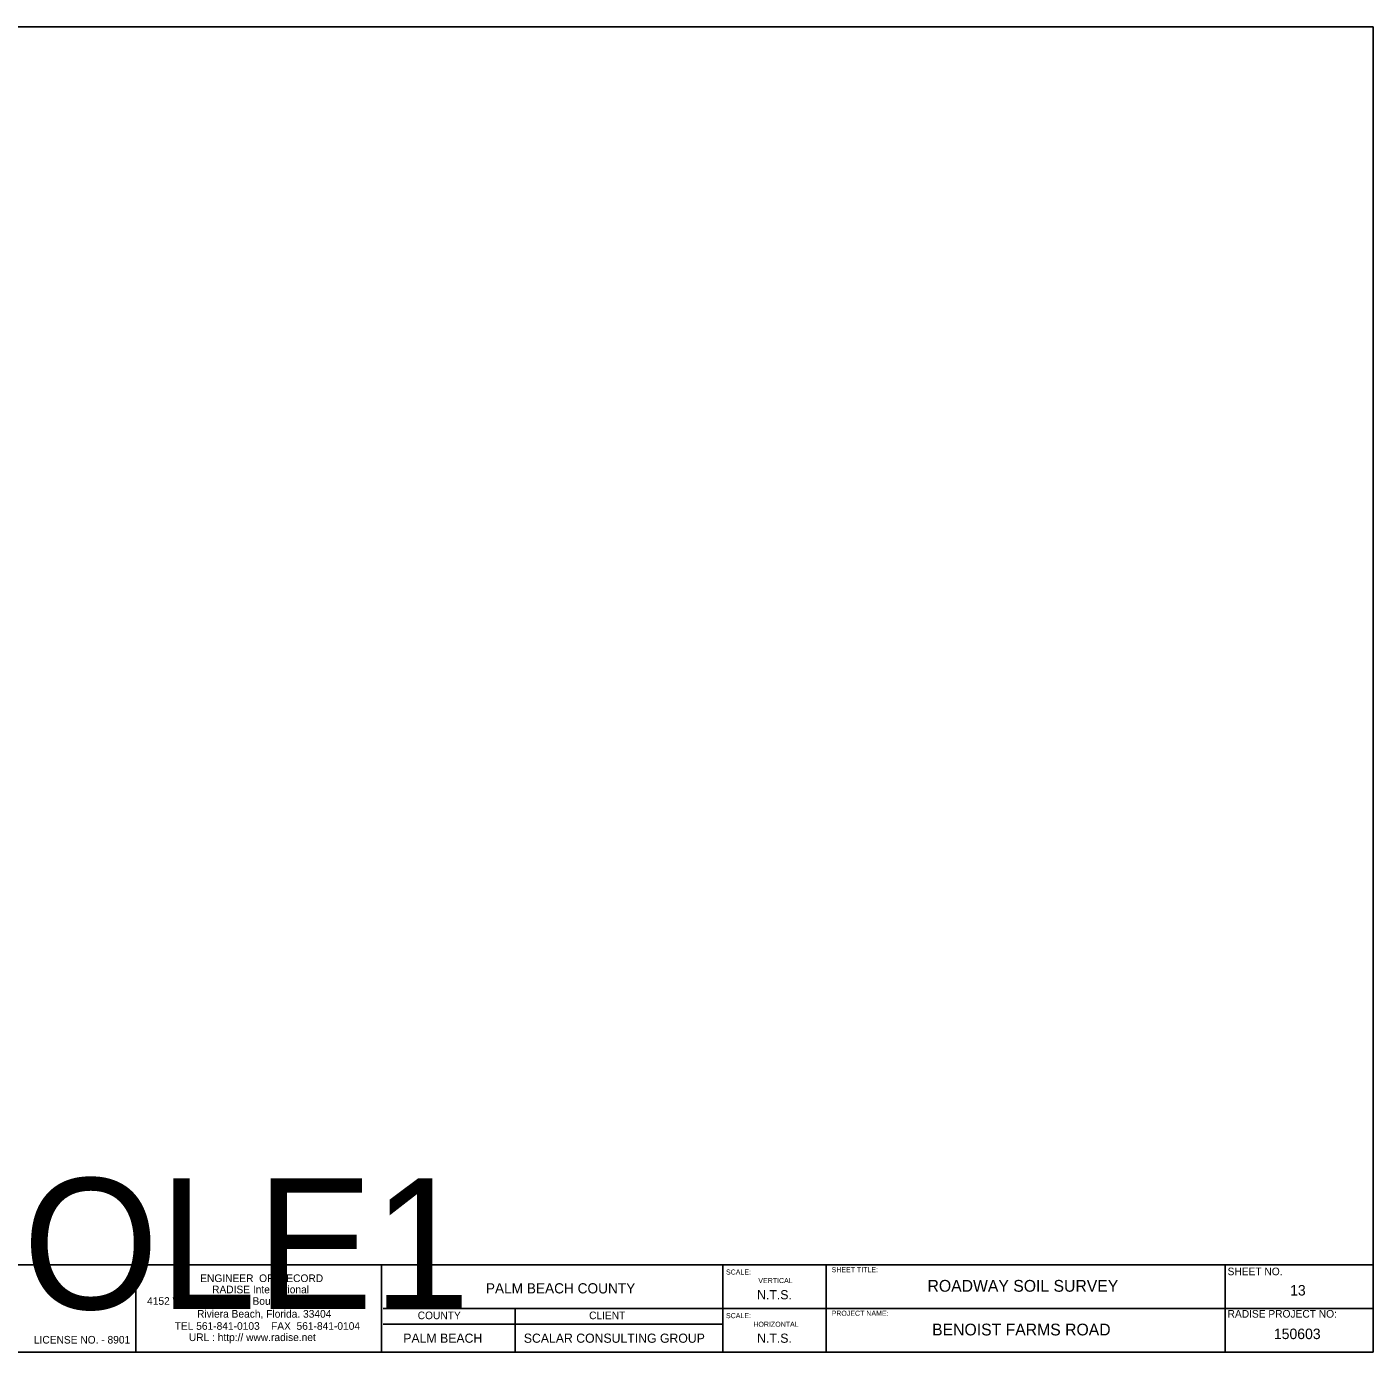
# Model space of a CAD drawing. Extents: x 0.6 to 16.4, y 0.2 to 10.3.
# Drawn here: x 6.16 to 16.45, y 0.16 to 10.29 of the extents above; entities that cross this region are included whole.
import ezdxf

# ---------------------------------------------------------------- set-up
doc = ezdxf.new("R2010")
doc.units = 0
for name, color, linetype in [('Level 1', 7, 'Continuous'), ('Level 23', 7, 'Continuous'), ('Level 24', 7, 'Continuous'), ('Level 46', 7, 'Continuous'), ('Level 63', 7, 'Continuous')]:
    doc.layers.add(name, color=color, linetype=linetype)

msp = doc.modelspace()

# ---------------------------------------------------------------- linework, layer by layer
at = {"layer": 'Level 23'}
for p, q in [((16.447, 0.161), (16.447, 10.287)), ((6.992, 0.161), (6.992, 0.827)), ((6.992, 0.161), (6.992, 0.827)), ((8.869, 0.161), (8.869, 0.827)), ((8.869, 0.161), (8.869, 0.827)), ((11.478, 0.161), (11.478, 0.827)), ((11.478, 0.161), (11.478, 0.827)), ((11.478, 0.161), (11.478, 0.827)), ((11.478, 0.161), (11.478, 0.827)), ((11.478, 0.161), (11.478, 0.827)), ((12.268, 0.161), (12.268, 0.827)), ((12.268, 0.161), (12.268, 0.827)), ((15.317, 0.161), (15.317, 0.827)), ((15.317, 0.161), (15.317, 0.827)), ((8.883, 0.494), (11.478, 0.494)), ((8.883, 0.494), (11.478, 0.494)), ((9.89, 0.494), (9.89, 0.161)), ((11.478, 0.494), (15.317, 0.494)), ((11.478, 0.494), (15.317, 0.494)), ((15.317, 0.494), (16.447, 0.494)), ((15.317, 0.494), (16.447, 0.494)), ((8.883, 0.373), (11.478, 0.373)), ((8.883, 0.373), (11.478, 0.373)), ((0.575, 0.161), (16.447, 0.161))]:
    msp.add_line(p, q, dxfattribs=at)
at = {"layer": 'Level 46'}
msp.add_line((0.573, 0.827), (16.447, 0.827), dxfattribs=at)
msp.add_line((0.573, 0.827), (16.447, 0.827), dxfattribs=at)
at = {"layer": 'Level 63'}
msp.add_lwpolyline([(0.575, 0.161), (16.447, 0.161), (16.447, 10.287), (0.575, 10.287), (0.575, 0.161)], dxfattribs=at)

# ---------------------------------------------------------------- texts
at = {"layer": 'Level 1'}
msp.add_text('OLE1', height=1, dxfattribs=at).set_placement((6.128, 0.489))
at = {"layer": 'Level 23'}
for s, height, p in [('ENGINEER  OF  RECORD', 0.05827, (7.484, 0.696)), ('SCALE:', 0.0389, (11.502, 0.753)), ('SCALE:', 0.0389, (11.502, 0.753)), ('SCALE:', 0.0389, (11.502, 0.753)), ('SCALE:', 0.0389, (11.502, 0.753)), ('SHEET TITLE:', 0.03887, (12.309, 0.771)), ('SHEET NO.', 0.0583, (15.335, 0.748)), ('RADISE International', 0.05827, (7.575, 0.61)), ('4152 West Blue Heron Boulevard, Suite 1114', 0.05827, (7.078, 0.522)), ('Riviera Beach, Florida. 33404', 0.05827, (7.46, 0.424)), ('COUNTY', 0.0583, (9.146, 0.412)), ('CLIENT', 0.0583, (10.456, 0.412)), ('SCALE:', 0.0389, (11.502, 0.42)), ('SCALE:', 0.0389, (11.502, 0.42)), ('SCALE:', 0.0389, (11.502, 0.42)), ('SCALE:', 0.0389, (11.502, 0.42)), ('PROJECT NAME:', 0.03887, (12.309, 0.438)), ('RADISE PROJECT NO:', 0.05827, (15.335, 0.424)), ('TEL 561-841-0103    FAX  561-841-0104', 0.05827, (7.289, 0.331)), ('LICENSE NO. - 8901', 0.05827, (6.213, 0.226)), ('                                                                URL : http:// www.radise.net', 0.05827, (6.012, 0.245))]:
    msp.add_text(s, height=height, dxfattribs=at).set_placement(p)
at = {"layer": 'Level 24'}
for s, height, p in [('VERTICAL', 0.0389, (11.749, 0.688)), ('PALM BEACH COUNTY ', 0.078, (9.667, 0.609)), ('N.T.S.', 0.07, (11.74, 0.564)), ('ROADWAY SOIL SURVEY', 0.09, (13.042, 0.622)), ('13', 0.08, (15.813, 0.593)), ('HORIZONTAL', 0.0389, (11.711, 0.354)), ('BENOIST FARMS ROAD', 0.09, (13.077, 0.288)), ('150603', 0.08, (15.689, 0.26)), ('PALM BEACH', 0.07, (9.036, 0.232)), ('SCALAR CONSULTING GROUP', 0.07, (9.957, 0.232)), ('N.T.S.', 0.07, (11.74, 0.232))]:
    msp.add_text(s, height=height, dxfattribs=at).set_placement(p)

doc.saveas('drawing.dxf')
